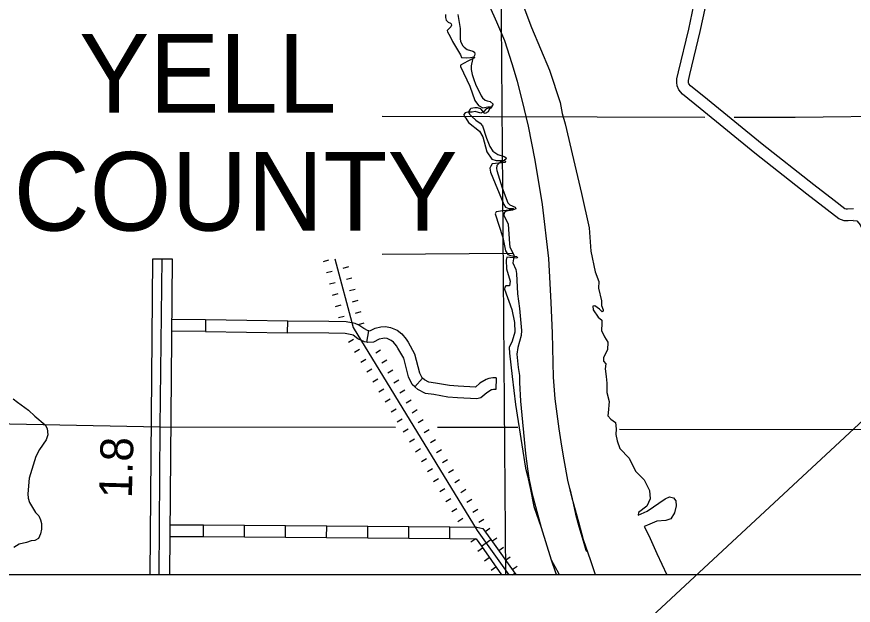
# Model space of a CAD drawing. Extents: x 1374139 to 1377472, y 1168351 to 1170484.
# Drawn here: x 1375154.2 to 1375369.3, y 1168645.9 to 1168797.3 of the extents above; entities that cross this region are included whole.
import ezdxf

# ---------------------------------------------------------------- set-up
doc = ezdxf.new("R2010")
doc.units = 0
for name, color, linetype in [('14', 7, 'Continuous'), ('26', 7, 'Continuous'), ('Default', 7, 'Continuous')]:
    doc.layers.add(name, color=color, linetype=linetype)

msp = doc.modelspace()

# ---------------------------------------------------------------- linework, layer by layer
at = {"layer": '14'}
msp.add_line((1375274.8, 1168603.49), (1375818.68, 1169108.27), dxfattribs=at)
at = {"layer": '26'}
msp.add_lwpolyline([(1375090, 1169579.43), (1376597.43, 1169579.43), (1376597.43, 1168653.79), (1375090, 1168653.79)], close=True, dxfattribs=at)
at = {"layer": 'Default'}
for p, q in [((1375188.5, 1168653.79), (1375189.19, 1168735.05)), ((1375189.19, 1168735.05), (1375194.19, 1168735.05)), ((1375194.19, 1168735.05), (1375193.5, 1168653.79)), ((1375233.05, 1168734.36), (1375234.5, 1168734.75)), ((1375238.18, 1168732.64), (1375239.63, 1168733.03)), ((1375233.84, 1168731.46), (1375235.28, 1168731.85)), ((1375234.62, 1168728.57), (1375236.07, 1168728.96)), ((1375238.96, 1168729.74), (1375240.41, 1168730.13)), ((1375239.74, 1168726.84), (1375241.19, 1168727.23)), ((1375235.4, 1168725.67), (1375236.85, 1168726.06)), ((1375240.53, 1168723.95), (1375241.97, 1168724.34)), ((1375236.18, 1168722.77), (1375237.63, 1168723.16)), ((1375236.96, 1168719.88), (1375238.41, 1168720.27)), ((1375241.31, 1168721.05), (1375242.75, 1168721.44)), ((1375202.79, 1168719.28), (1375202.76, 1168716.28)), ((1375223.87, 1168716.02), (1375223.91, 1168719.02)), ((1375242.09, 1168718.15), (1375243.54, 1168718.54)), ((1375223.87, 1168716.02), (1375223.87, 1168716.02)), ((1375244.19, 1168713.55), (1375244.75, 1168716.49)), ((1375239.53, 1168713.59), (1375240.82, 1168714.37)), ((1375244.19, 1168713.55), (1375244.19, 1168713.55)), ((1375241.1, 1168711.03), (1375242.38, 1168711.81)), ((1375246.5, 1168710.81), (1375247.78, 1168711.6)), ((1375242.66, 1168708.47), (1375243.94, 1168709.25)), ((1375248.06, 1168708.25), (1375249.34, 1168709.04)), ((1375244.22, 1168705.91), (1375245.5, 1168706.69)), ((1375249.63, 1168705.69), (1375250.91, 1168706.47)), ((1375245.78, 1168703.35), (1375247.06, 1168704.13)), ((1375251.19, 1168703.13), (1375252.47, 1168703.91)), ((1375258.57, 1168704.31), (1375256.57, 1168702.08)), ((1375277.51, 1168704.38), (1375277.38, 1168701.38)), ((1375247.35, 1168700.79), (1375248.63, 1168701.57)), ((1375252.75, 1168700.57), (1375254.03, 1168701.35)), ((1375248.91, 1168698.23), (1375250.19, 1168699.01)), ((1375254.31, 1168698.01), (1375255.59, 1168698.79)), ((1375250.47, 1168695.67), (1375251.75, 1168696.45)), ((1375255.88, 1168695.45), (1375257.16, 1168696.23)), ((1375252.03, 1168693.11), (1375253.31, 1168693.89)), ((1375257.44, 1168692.89), (1375258.72, 1168693.67)), ((1375253.6, 1168690.54), (1375254.88, 1168691.33)), ((1375259, 1168690.33), (1375260.28, 1168691.11)), ((1375255.16, 1168687.98), (1375256.44, 1168688.76)), ((1375260.56, 1168687.77), (1375261.84, 1168688.55)), ((1375256.72, 1168685.42), (1375258, 1168686.2)), ((1375262.13, 1168685.21), (1375263.41, 1168685.99)), ((1375258.28, 1168682.86), (1375259.56, 1168683.64)), ((1375263.69, 1168682.64), (1375264.97, 1168683.43)), ((1375259.85, 1168680.3), (1375261.13, 1168681.08)), ((1375265.25, 1168680.08), (1375266.53, 1168680.86)), ((1375261.41, 1168677.74), (1375262.69, 1168678.52)), ((1375266.81, 1168677.52), (1375268.09, 1168678.3)), ((1375262.97, 1168675.18), (1375264.25, 1168675.96)), ((1375268.38, 1168674.96), (1375269.66, 1168675.74)), ((1375264.53, 1168672.62), (1375265.81, 1168673.4)), ((1375269.94, 1168672.4), (1375271.22, 1168673.18)), ((1375266.1, 1168670.06), (1375267.38, 1168670.84)), ((1375271.5, 1168669.84), (1375272.78, 1168670.62)), ((1375202.22, 1168663.57), (1375202.24, 1168666.57)), ((1375212.78, 1168663.49), (1375212.8, 1168666.49)), ((1375223.34, 1168663.41), (1375223.36, 1168666.41)), ((1375233.9, 1168663.33), (1375233.92, 1168666.33)), ((1375244.46, 1168663.25), (1375244.48, 1168666.25)), ((1375267.66, 1168667.5), (1375268.94, 1168668.28)), ((1375273.06, 1168667.28), (1375274.34, 1168668.06)), ((1375255.02, 1168663.17), (1375255.04, 1168666.17)), ((1375265.58, 1168663.09), (1375265.6, 1168666.09)), ((1375274.65, 1168664.86), (1375275.87, 1168665.73)), ((1375270.99, 1168662.25), (1375272.21, 1168663.12)), ((1375273.7, 1168661.08), (1375276.14, 1168662.82)), ((1375276.39, 1168662.42), (1375277.62, 1168663.29)), ((1375272.73, 1168659.81), (1375273.95, 1168660.68)), ((1375278.13, 1168659.98), (1375279.36, 1168660.85)), ((1375274.47, 1168657.37), (1375275.69, 1168658.24)), ((1375279.87, 1168657.53), (1375281.1, 1168658.4)), ((1375276.21, 1168654.92), (1375277.43, 1168655.79)), ((1375281.62, 1168655.09), (1375282.84, 1168655.96)), ((1375193.5, 1168653.79), (1375188.5, 1168653.79)), ((1375281.66, 1168653.79), (1375282.27, 1168654.22))]:
    msp.add_line(p, q, dxfattribs=at)
for points in [[(1375278.34, 1168851.32), (1375279.88, 1168653.79)], [(1375303.05, 1168653.79), (1375301.79, 1168657.34), (1375299.96, 1168662.77), (1375298.69, 1168667.25), (1375297.03, 1168673.45), (1375295.91, 1168678.1), (1375294.96, 1168683.35), (1375294.37, 1168686.85), (1375293.68, 1168691.26), (1375292.68, 1168699.01), (1375292.25, 1168704.56), (1375291.96, 1168715.86), (1375291.58, 1168723.75), (1375291.38, 1168728.64), (1375291.04, 1168735.1), (1375289.39, 1168748.99), (1375287.51, 1168760.37), (1375285.76, 1168769.14), (1375284.24, 1168775.57), (1375283, 1168780.62), (1375281.63, 1168785.13), (1375279.69, 1168791.06), (1375277.65, 1168795.85), (1375275.82, 1168799.93)], [(1375284.37, 1168800.39), (1375286.55, 1168794.48), (1375291.16, 1168783.54), (1375293.92, 1168775.19), (1375294.48, 1168772.34), (1375295.23, 1168769.72), (1375297.33, 1168760.53), (1375299.43, 1168751.8), (1375301.38, 1168742.95), (1375301.78, 1168736.94), (1375302.9, 1168731.65), (1375303.87, 1168729.2), (1375303.8, 1168727.47), (1375304.55, 1168724.2), (1375304.52, 1168723.02), (1375304.97, 1168721.89), (1375304.95, 1168721.57), (1375304.7, 1168721.34), (1375304.07, 1168722.07), (1375302.86, 1168722.88)], [(1375369.27, 1168744.86), (1375367.94, 1168744.75), (1375366.92, 1168744.75), (1375365.57, 1168745.26), (1375362.57, 1168747.62), (1375357.32, 1168751.67), (1375343.97, 1168762.19), (1375329.89, 1168773.65), (1375325.35, 1168777.36), (1375324.44, 1168778.45), (1375324, 1168779.48), (1375323.89, 1168780.32), (1375323.94, 1168781.29), (1375324.34, 1168783.12), (1375327, 1168794.09), (1375328.31, 1168800.22)], [(1375369.31, 1168747.88), (1375367.81, 1168747.75), (1375367.48, 1168747.75), (1375367.07, 1168747.9), (1375364.41, 1168749.99), (1375359.16, 1168754.03), (1375345.85, 1168764.53), (1375331.78, 1168775.97), (1375327.47, 1168779.5), (1375327.03, 1168780.03), (1375326.92, 1168780.28), (1375326.9, 1168780.45), (1375326.92, 1168780.9), (1375327.26, 1168782.44), (1375329.92, 1168793.43), (1375331.27, 1168799.73)], [(1375264.45, 1168797.82), (1375264.42, 1168797.1), (1375264.65, 1168796.36), (1375265.11, 1168795.88), (1375265.73, 1168795.57), (1375265.93, 1168795.41), (1375265.99, 1168795.06), (1375265.83, 1168794.67), (1375265.21, 1168794.05), (1375264.86, 1168793.72), (1375264.98, 1168793.34), (1375265.62, 1168792.15), (1375266.22, 1168790.91), (1375268.32, 1168787.46), (1375268.57, 1168786.75), (1375269.77, 1168786.67), (1375270.92, 1168786.75), (1375271.75, 1168786.94), (1375271.96, 1168786.82), (1375271.89, 1168786.67), (1375270.18, 1168785.81), (1375268.28, 1168784.78), (1375268.32, 1168784.45), (1375270.7, 1168779.38), (1375272.02, 1168775.75), (1375272.91, 1168774.41), (1375274.08, 1168773.83), (1375275.34, 1168774.09), (1375276.24, 1168774.06), (1375276.31, 1168773.91), (1375276.19, 1168773.79), (1375275.34, 1168773.69), (1375274.91, 1168773.59), (1375274.34, 1168772.91), (1375273.51, 1168772.46), (1375272.04, 1168772.86), (1375271.31, 1168772.69), (1375270.16, 1168772.74), (1375269.49, 1168772.54), (1375269.16, 1168772.11), (1375269.21, 1168771.71), (1375269.64, 1168771.14), (1375270.39, 1168770.09), (1375273.19, 1168767.81), (1375274.06, 1168766.38), (1375275.11, 1168762.51), (1375276.34, 1168760.61), (1375277.49, 1168760.31), (1375279.39, 1168760.26), (1375279.76, 1168760.23), (1375279.86, 1168760.06), (1375279.74, 1168759.76), (1375278.94, 1168759.66)], [(1375267.61, 1168797.84), (1375268.19, 1168794.22), (1375268.18, 1168791.67), (1375268.31, 1168790.91), (1375268.87, 1168789.76), (1375269.21, 1168789.4), (1375270.06, 1168788.81), (1375271.45, 1168788.4), (1375271.89, 1168788.12), (1375272.02, 1168787.66), (1375271.94, 1168787.26), (1375271.42, 1168786.29), (1375271.07, 1168784.62), (1375271.05, 1168783.68), (1375271.31, 1168782.42), (1375271.71, 1168781.14), (1375272.17, 1168779.89), (1375273.61, 1168776.9), (1375273.94, 1168776.43), (1375274.61, 1168775.84), (1375275.13, 1168775.6), (1375275.94, 1168775.44), (1375276.69, 1168774.79), (1375276.08, 1168773.82), (1375275.71, 1168773.41), (1375275.46, 1168772.84), (1375274.67, 1168772.39), (1375274.47, 1168772.45), (1375273.55, 1168773.55), (1375272.71, 1168773.86), (1375272.01, 1168773.85), (1375270.99, 1168773.65), (1375270.78, 1168773.47), (1375270.39, 1168772.82), (1375270.66, 1168772.18), (1375271.21, 1168771.57), (1375272.24, 1168770.69), (1375273.39, 1168769.92), (1375273.96, 1168769.25), (1375274.95, 1168766.06), (1375275.81, 1168763.89), (1375276.63, 1168762.68), (1375277.92, 1168761.86), (1375279.57, 1168761.34), (1375279.95, 1168761.05), (1375280.06, 1168760.73), (1375279.13, 1168759.97), (1375278.55, 1168759.98)], [(1375248.21, 1168771.66), (1375331.15, 1168771.47)], [(1375338.65, 1168771.45), (1375354.31, 1168771.42), (1375383.06, 1168771.77), (1375434.37, 1168771.58)], [(1375278.94, 1168759.66), (1375276.46, 1168759.48), (1375276.14, 1168758.83), (1375275.89, 1168758.33), (1375276.04, 1168757.28), (1375279.44, 1168748.95), (1375279.91, 1168748.27), (1375280.76, 1168747.97), (1375281.86, 1168747.95), (1375281.99, 1168747.75), (1375281.69, 1168747.65), (1375279.21, 1168747.37), (1375277.51, 1168747.12), (1375277.26, 1168746.6), (1375279.21, 1168740.46), (1375279.91, 1168737.1), (1375280.51, 1168736.15), (1375281.16, 1168735.9), (1375282.81, 1168735.58), (1375282.96, 1168735.3), (1375282.61, 1168735.18), (1375280.24, 1168735.43), (1375280.04, 1168734.67), (1375280.14, 1168732.44), (1375281.06, 1168729.24), (1375280.91, 1168728.06), (1375280.46, 1168728.04), (1375279.99, 1168728.04), (1375279.69, 1168727.76), (1375279.64, 1168727.21), (1375281.54, 1168721.94), (1375282.19, 1168718.6), (1375282.24, 1168716.12), (1375281.56, 1168713.87), (1375280.84, 1168712.18), (1375280.91, 1168710.71), (1375281.59, 1168704.75), (1375282.49, 1168697.54), (1375284.09, 1168687.14), (1375285.06, 1168681.18), (1375285.49, 1168679.18), (1375286.31, 1168675.68), (1375287.19, 1168671.35), (1375289.08, 1168665.93), (1375291.6, 1168657.61), (1375293.52, 1168654.14), (1375293.67, 1168653.79)], [(1375278.55, 1168759.98), (1375277.67, 1168758.99), (1375277.6, 1168758.22), (1375277.67, 1168757.76), (1375279.06, 1168753.23), (1375280.46, 1168749.41), (1375280.99, 1168748.88), (1375282.38, 1168748.28), (1375282.55, 1168747.86), (1375281.71, 1168747.54), (1375280.08, 1168747.26), (1375279.57, 1168746.85), (1375279.44, 1168746.28), (1375280.56, 1168743.94), (1375280.88, 1168738.89), (1375281.01, 1168738.13), (1375281.99, 1168735.98), (1375282.03, 1168735.56), (1375281.76, 1168733.97), (1375282.53, 1168732.28), (1375282.72, 1168731.2), (1375282.93, 1168725.99), (1375283.47, 1168722.27), (1375284.01, 1168716.61), (1375283.93, 1168715.26), (1375283.04, 1168712.22), (1375282.83, 1168710.47), (1375283.15, 1168707.05), (1375283.5, 1168704.97), (1375283.45, 1168703.17), (1375283.77, 1168698.4), (1375284.99, 1168684.97), (1375285.5, 1168680.99), (1375285.9, 1168678.61), (1375286.76, 1168674.47), (1375289.08, 1168665.93), (1375291.6, 1168657.61), (1375292.75, 1168654.36), (1375293, 1168653.79)], [(1375369.27, 1168744.86), (1375370.18, 1168744.76), (1375370.27, 1168744.7), (1375371.02, 1168743.78), (1375371.62, 1168742.48), (1375376.13, 1168732.94), (1375378.56, 1168728.31), (1375382.21, 1168722.9), (1375384.42, 1168719.41), (1375385.26, 1168718.28), (1375386.31, 1168717.37), (1375387.38, 1168717.14), (1375388.97, 1168717.09), (1375397.36, 1168717.09), (1375407.6, 1168717.01), (1375421.54, 1168716.89), (1375429.68, 1168716.81), (1375433.87, 1168716.96)], [(1375191.1, 1168691.79), (1375191.63, 1168735.05)], [(1375235.98, 1168735.05), (1375240.75, 1168717.37), (1375272.59, 1168665.17), (1375280.7, 1168653.79)], [(1375248.21, 1168736.17), (1375281.67, 1168736.46)], [(1375302.86, 1168722.88), (1375302.36, 1168722.83), (1375302.41, 1168721.88), (1375303.66, 1168720.01), (1375304.6, 1168719.27), (1375304.66, 1168718.36), (1375304.56, 1168716.61), (1375305.36, 1168714.91), (1375306.16, 1168713.56), (1375306.06, 1168711.61), (1375305.06, 1168709.66), (1375305.11, 1168708.66), (1375305.66, 1168708.01), (1375305.46, 1168706.71), (1375305.76, 1168704.75), (1375305.96, 1168703), (1375305.91, 1168700.65), (1375306.51, 1168698.33), (1375306.31, 1168695.43), (1375306.21, 1168694.63), (1375306.96, 1168693.78), (1375308.16, 1168692.93), (1375308.36, 1168691.28), (1375308.21, 1168689.83), (1375308.61, 1168688.17), (1375309.31, 1168686.27), (1375311.71, 1168683.77), (1375313.26, 1168680.37), (1375315.51, 1168678.17), (1375316.91, 1168675.47), (1375317.11, 1168673.31), (1375316.21, 1168671.41), (1375314.06, 1168669.81), (1375314.01, 1168669.11), (1375316.26, 1168670.11), (1375320.96, 1168673.26), (1375322.01, 1168673.81), (1375323.06, 1168673.56), (1375323.66, 1168672.76), (1375323.76, 1168671.51), (1375323.31, 1168669.71), (1375322.36, 1168668.16), (1375321.06, 1168667.71), (1375318.76, 1168667.51), (1375316.41, 1168666.56), (1375315.56, 1168666.16), (1375316.71, 1168663.86), (1375318.76, 1168659.2), (1375321.35, 1168653.79)], [(1375202.79, 1168719.28), (1375194.06, 1168719.38)], [(1375213.35, 1168719.15), (1375202.79, 1168719.28)], [(1375223.91, 1168719.02), (1375213.35, 1168719.15)], [(1375234.47, 1168718.89), (1375223.91, 1168719.02)], [(1375244.75, 1168716.49), (1375244.59, 1168716.52), (1375243.48, 1168717.06), (1375242.17, 1168717.99), (1375241.23, 1168718.39), (1375238.92, 1168718.83), (1375234.47, 1168718.89)], [(1375202.76, 1168716.28), (1375194.03, 1168716.38)], [(1375202.76, 1168716.28), (1375213.32, 1168716.15)], [(1375213.32, 1168716.15), (1375223.87, 1168716.02)], [(1375234.43, 1168715.89), (1375223.87, 1168716.02)], [(1375244.19, 1168713.55), (1375243.65, 1168713.65), (1375241.95, 1168714.46), (1375240.69, 1168715.36), (1375240.35, 1168715.5), (1375238.62, 1168715.83), (1375234.43, 1168715.89)], [(1375244.75, 1168716.49), (1375244.6, 1168716.52), (1375245.18, 1168716.57), (1375246.4, 1168717.14), (1375247.84, 1168717.52), (1375249, 1168717.64), (1375250.3, 1168717.37), (1375252.03, 1168716.67), (1375253.19, 1168715.74), (1375254.35, 1168714.37), (1375254.82, 1168713.55)], [(1375252.22, 1168712.06), (1375251.89, 1168712.64), (1375251.09, 1168713.58), (1375250.5, 1168714.05), (1375249.43, 1168714.49), (1375248.85, 1168714.61), (1375248.37, 1168714.56), (1375247.42, 1168714.31), (1375245.97, 1168713.62), (1375244.44, 1168713.5), (1375244.19, 1168713.55)], [(1375254.82, 1168713.55), (1375256.52, 1168710.59), (1375257.81, 1168705.66), (1375258.34, 1168704.53), (1375258.57, 1168704.31)], [(1375256.57, 1168702.08), (1375255.87, 1168702.71), (1375254.98, 1168704.65), (1375253.72, 1168709.44), (1375252.22, 1168712.06)], [(1375267.74, 1168702.29), (1375265.44, 1168702.44), (1375261.9, 1168703.07), (1375260.19, 1168703.29), (1375259.07, 1168703.87), (1375258.57, 1168704.31)], [(1375277.51, 1168704.38), (1375276.61, 1168704.42), (1375275.6, 1168704.26), (1375274.9, 1168703.97), (1375273.27, 1168703.01), (1375272.14, 1168702), (1375267.74, 1168702.29)], [(1375267.54, 1168699.3), (1375265.07, 1168699.46), (1375261.45, 1168700.1), (1375259.28, 1168700.38), (1375257.35, 1168701.38), (1375256.57, 1168702.08)], [(1375277.38, 1168701.38), (1375276.77, 1168701.41), (1375276.42, 1168701.35), (1375276.24, 1168701.28), (1375275.05, 1168700.58), (1375273.57, 1168699.25), (1375272.55, 1168698.97), (1375267.54, 1168699.3)], [(1375153.35, 1168699.01), (1375154.42, 1168698.12), (1375157.21, 1168696.12), (1375158.88, 1168694.51), (1375161.55, 1168692.36), (1375162.02, 1168691.36), (1375162.21, 1168689.78), (1375161.8, 1168688.45), (1375160.08, 1168685.96), (1375159.13, 1168684.21), (1375157.42, 1168678.57), (1375157.05, 1168674.6), (1375157.2, 1168673.45), (1375157.54, 1168672.39), (1375159.08, 1168669.82), (1375159.87, 1168668.9), (1375160.37, 1168667.91), (1375160.56, 1168666.97), (1375160.55, 1168665.48), (1375160.34, 1168664.32), (1375159.85, 1168663.09), (1375158.91, 1168662.61), (1375157.92, 1168662.46), (1375156.7, 1168662.03), (1375154.85, 1168661.6), (1375153.47, 1168660.78)], [(1375100.74, 1168693.63), (1375191.1, 1168691.79), (1375251.59, 1168691.75)], [(1375190.88, 1168653.79), (1375191.1, 1168691.79)], [(1375262.43, 1168691.74), (1375283.08, 1168691.73)], [(1375309.16, 1168691.25), (1375382.61, 1168691.1)], [(1375296.43, 1168675.83), (1375297.29, 1168672.16), (1375297.91, 1168669.38), (1375298.73, 1168666.18), (1375299.81, 1168662.53), (1375300.57, 1168660.1), (1375300.69, 1168659.73)], [(1375193.61, 1168666.64), (1375202.24, 1168666.57)], [(1375202.24, 1168666.57), (1375212.8, 1168666.49)], [(1375212.8, 1168666.49), (1375223.36, 1168666.41)], [(1375223.36, 1168666.41), (1375233.92, 1168666.33)], [(1375233.92, 1168666.33), (1375244.48, 1168666.25)], [(1375244.48, 1168666.25), (1375255.04, 1168666.17)], [(1375255.04, 1168666.17), (1375265.6, 1168666.09)], [(1375265.6, 1168666.09), (1375272.55, 1168666.04), (1375274.09, 1168665.7), (1375276.14, 1168662.82)], [(1375193.58, 1168663.64), (1375202.22, 1168663.57)], [(1375202.22, 1168663.57), (1375212.78, 1168663.49)], [(1375212.78, 1168663.49), (1375223.34, 1168663.41)], [(1375223.34, 1168663.41), (1375233.9, 1168663.33)], [(1375233.9, 1168663.33), (1375244.46, 1168663.25)], [(1375244.46, 1168663.25), (1375255.02, 1168663.17)], [(1375255.02, 1168663.17), (1375265.58, 1168663.09)], [(1375265.58, 1168663.09), (1375272.21, 1168663.04), (1375272.32, 1168663.02), (1375273.7, 1168661.08)], [(1375276.14, 1168662.82), (1375282.27, 1168654.22)], [(1375273.7, 1168661.08), (1375278.89, 1168653.79)], [(1375282.27, 1168654.22), (1375282.58, 1168653.79)]]:
    msp.add_lwpolyline(points, dxfattribs=at)

# ---------------------------------------------------------------- texts
for s, p in [('YELL', (1375170.27, 1168772.59)), ('COUNTY', (1375153.44, 1168742.27))]:
    msp.add_text(s, height=20.215, dxfattribs=at).set_placement(p)
msp.add_text('1.8', height=8.448, rotation=88.3984, dxfattribs=at).set_placement((1375183.81, 1168673.37))

doc.saveas('drawing.dxf')
